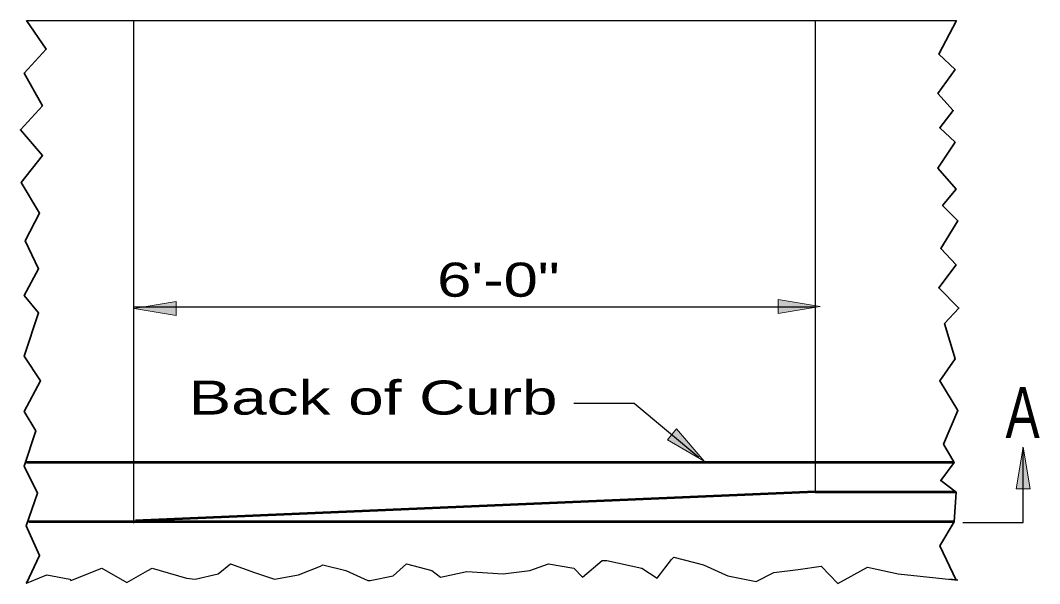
# Model space of a CAD drawing. Extents: x 75.6 to 110.9, y 28 to 50.
# Drawn here: x 98.168 to 102.654, y 42.626 to 45.106 of the extents above; entities that cross this region are included whole.
import ezdxf
from ezdxf.enums import TextEntityAlignment as Align

# ---------------------------------------------------------------- set-up
doc = ezdxf.new("R2010")
doc.units = 0
doc.header["$LTSCALE"] = 0.06
doc.layers.add('1', color=7, linetype='Continuous', lineweight=25)
doc.layers.add('3', color=7, linetype='Continuous', lineweight=13)

msp = doc.modelspace()

# ---------------------------------------------------------------- hatches: boundary and pattern name
at = {"layer": '3'}
for points in [[(101.50342, 43.87658), (101.50342, 43.815), (101.688, 43.84583), (101.688, 43.84583)], [(98.85425, 43.8685), (98.85425, 43.80692), (98.66967, 43.83775), (98.66967, 43.83775)], [(101.056, 43.307), (101.01642, 43.25992), (101.1775, 43.16458), (101.1775, 43.16458)], [(102.55183, 43.043), (102.61325, 43.043), (102.5825, 43.22758), (102.5825, 43.22758)]]:
    msp.add_hatch(color=256, dxfattribs=at).paths.add_polyline_path(points)

# ---------------------------------------------------------------- linework, layer by layer
at = {"layer": '1'}
for p, q in [((98.19525, 45.10633), (102.289, 45.10633)), ((98.66642, 45.10633), (98.66642, 42.89233)), ((101.66658, 45.10633), (101.66658, 43.03)), ((98.66642, 43.84475), (101.66658, 43.84475))]:
    msp.add_line(p, q, dxfattribs=at)
at = {"layer": '1', "lineweight": 53}
for p, q in [((98.19525, 43.16075), (102.27842, 43.16075)), ((101.66658, 43.03), (98.67483, 42.90225)), ((101.66658, 43.03), (102.28617, 43.03)), ((98.20492, 42.89917), (102.27925, 42.89917))]:
    msp.add_line(p, q, dxfattribs=at)
at = {"layer": '1', "lineweight": 35}
for points in [[(98.19525, 45.10633), (98.28233, 44.97917), (98.18525, 44.87367), (98.2655, 44.73008), (98.16842, 44.62458), (98.2655, 44.51058), (98.17258, 44.39233), (98.25283, 44.25733), (98.18958, 44.13492), (98.24858, 44.01242), (98.18525, 43.89425), (98.24858, 43.81833), (98.18525, 43.62833), (98.257, 43.51858), (98.18525, 43.3835), (98.23592, 43.299), (98.18525, 43.14283), (98.24442, 43.02467), (98.19375, 42.88117), (98.25283, 42.75025), (98.19525, 42.62783), (98.19525, 42.62783)], [(102.289, 45.10633), (102.21075, 44.958), (102.2825, 44.89058), (102.20658, 44.785), (102.274, 44.709), (102.21492, 44.633), (102.2825, 44.56967), (102.20658, 44.45567), (102.28667, 44.36283), (102.22758, 44.29108), (102.29517, 44.22358), (102.21925, 44.10108), (102.28667, 44.02933), (102.21075, 43.928), (102.29933, 43.83933), (102.236, 43.77183), (102.2825, 43.61567), (102.21492, 43.51858), (102.29517, 43.38767), (102.23183, 43.24), (102.27825, 43.15975), (102.21925, 43.07958), (102.28667, 43.02892), (102.27825, 42.898), (102.21492, 42.7925), (102.28667, 42.6405)]]:
    msp.add_lwpolyline(points, dxfattribs=at)
at = {"layer": '1'}
for points in [[(100.60467, 43.42017), (100.87042, 43.42017), (101.15475, 43.183)], [(102.31675, 42.895), (102.5825, 42.895), (102.5825, 43.22758)], [(98.19525, 42.62783), (98.28417, 42.66467), (98.38583, 42.64533), (98.39058, 42.64042), (98.52625, 42.69375), (98.63758, 42.63075), (98.72958, 42.684), (98.749, 42.69375), (98.89917, 42.65017), (98.93792, 42.64533), (99.03958, 42.66958), (99.09283, 42.71317), (99.19942, 42.67433), (99.28658, 42.64533), (99.39308, 42.66467), (99.48992, 42.70342), (99.49958, 42.70833), (99.60133, 42.684), (99.69825, 42.64042), (99.70792, 42.64042), (99.80958, 42.65983), (99.86767, 42.71317), (99.979, 42.684), (100.01783, 42.655), (100.134, 42.67925), (100.29383, 42.66958), (100.41, 42.684), (100.49242, 42.71317), (100.60383, 42.69375), (100.6425, 42.655), (100.72967, 42.72767), (100.749, 42.72767), (100.904, 42.69375), (100.97183, 42.65017), (101.03483, 42.7325), (101.04442, 42.74217), (101.17525, 42.70833), (101.272, 42.66467), (101.28175, 42.65983), (101.40758, 42.63567), (101.48517, 42.67433), (101.59167, 42.68892), (101.69342, 42.70342), (101.766, 42.626), (101.89683, 42.69858), (102.03242, 42.66958), (102.29517, 42.6405), (102.26, 42.64533)]]:
    msp.add_lwpolyline(points, dxfattribs=at)
at = {"layer": '3'}
for points in [[(101.50342, 43.87658), (101.50342, 43.815), (101.688, 43.84583), (101.688, 43.84583)], [(98.85425, 43.8685), (98.85425, 43.80692), (98.66967, 43.83775), (98.66967, 43.83775)], [(101.056, 43.307), (101.01642, 43.25992), (101.1775, 43.16458), (101.1775, 43.16458)], [(102.55183, 43.043), (102.61325, 43.043), (102.5825, 43.22758), (102.5825, 43.22758)]]:
    msp.add_lwpolyline(points, close=True, dxfattribs=at)

# ---------------------------------------------------------------- texts
at = {"layer": '1'}
for s, height, width, p in [('6\'-0"', 0.15, 1.35, (100.27246, 43.88942)), ('Back of Curb', 0.15, 1.4, (99.72058, 43.37025)), ('A', 0.225, 0.75, (102.57962, 43.26683))]:
    msp.add_text(s, height=height, dxfattribs=dict(at, width=width)).set_placement(p, align=Align.CENTER)

doc.saveas('drawing.dxf')
